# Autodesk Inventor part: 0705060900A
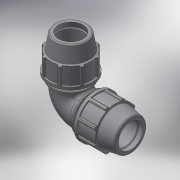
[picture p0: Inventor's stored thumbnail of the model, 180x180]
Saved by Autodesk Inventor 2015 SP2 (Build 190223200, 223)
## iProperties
Created: 2017-02
Part Number: 0705060900A
Material: Generic
Description: PLASSON 90° ELBOW 90-90
Document SubType Name: Modeling
Designer: KIM
Mass: 1923.39 g
Surface Area: 2516.77 cm^2
Volume: 1923.39 cm^3
Density: 1 g/cm^3
Appearance: Default
Author: KIM
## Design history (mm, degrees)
derived "87050.ipt"
feature "Solid1::87050.ipt"
tag "TaggingFeature1"
body "Solid1"
other parameters: "d4" = 18.08333, "d5" = 54.25, "d7" = 154, "d9" = 31, "d11" = 7.23333, "d13" = 120 deg, "d14" = 117, "d15" = 10 deg, "d16" = 133.98, "d18" = 4.5, "d19" = 35 deg, "d20" = 17.5 deg, "d21" = 143.22, "d23" = 0, "d25" = 360 deg, "d27" = 3.08, "d33" = 1.8, "d42" = 73.78, "d43" = 4.62, "d46" = 2.7, "d51" = 217, "d59" = 90 deg, "d63" = 162, "d64" = 81, "d67" = 115.5, "d68" = 13.02, "d70" = 90 deg, "d71" = 13.5, "d72" = 10.26667, "d73" = 0, "d75" = 90 deg, "d77" = 131.3004, "d78" = 4.34, "E_" = 154, "A_" = 217, "l_" = 162
